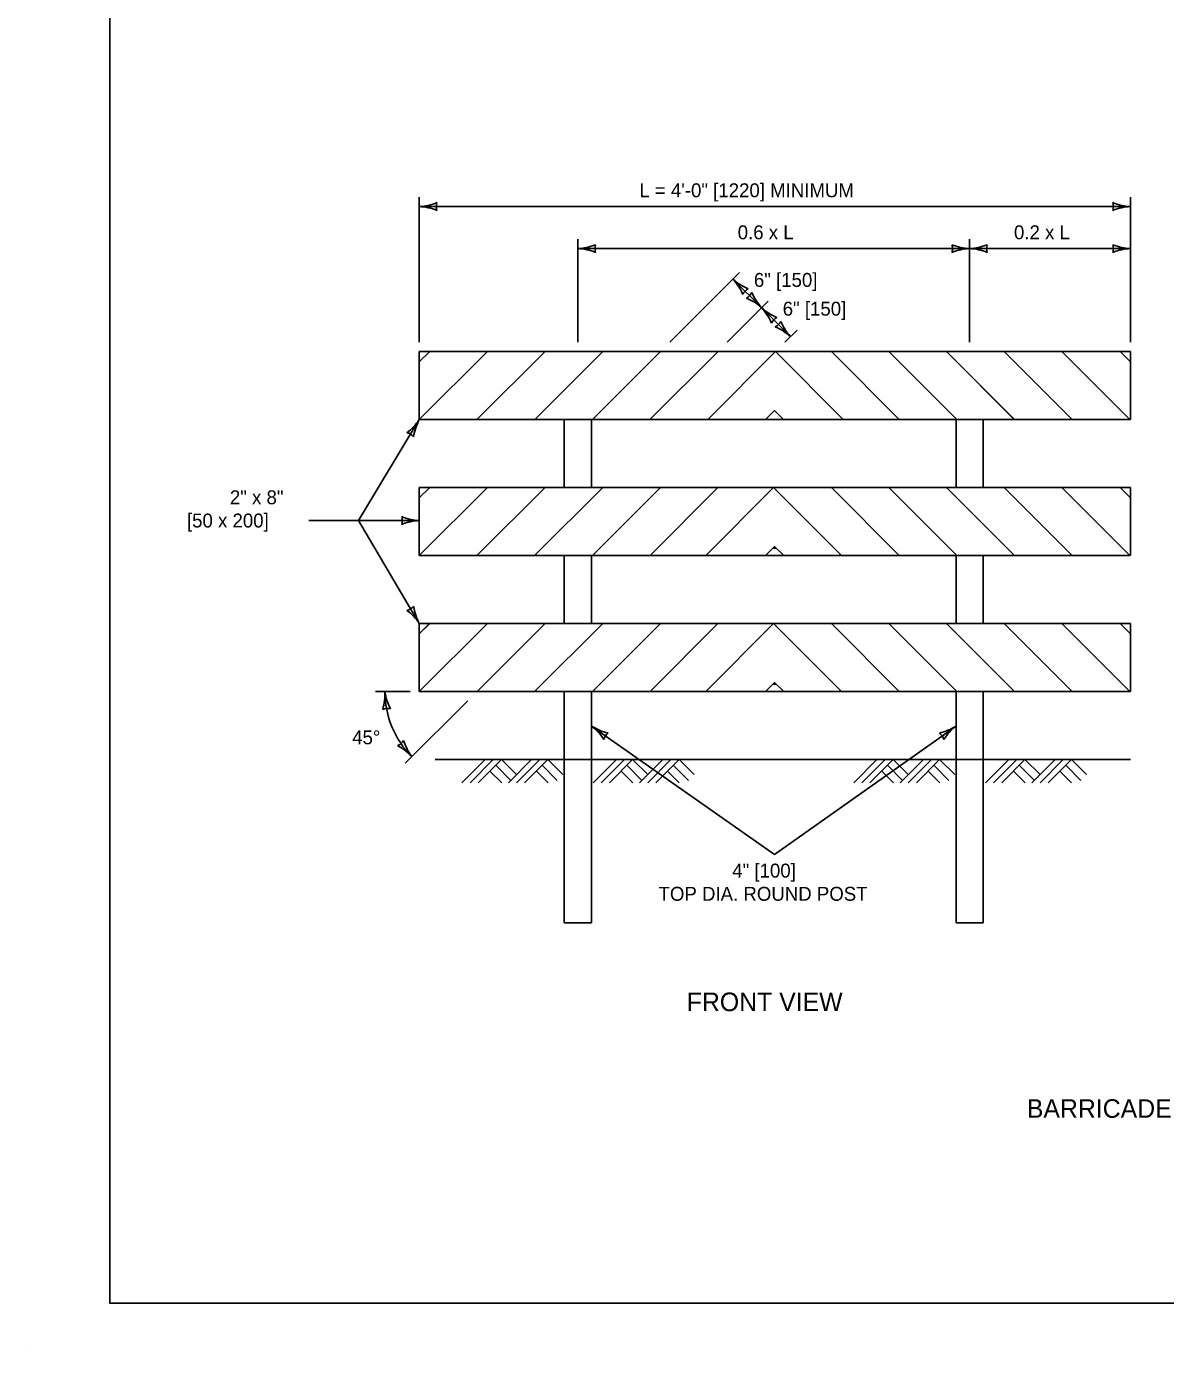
# Model space of a CAD drawing. Extents: x 49991.4 to 50021, y 49987.6 to 50011.4.
# Drawn here: x 49999.02 to 50003.93, y 49987.6 to 49993.3 of the extents above; entities that cross this region are included whole.
import ezdxf

# ---------------------------------------------------------------- set-up
doc = ezdxf.new("R2010")
doc.units = 0
for name, color, linetype in [('Level 1', 7, 'Continuous'), ('Level 2', 7, 'Continuous'), ('Level 3', 7, 'Continuous'), ('Level 4', 7, 'Continuous')]:
    doc.layers.add(name, color=color, linetype=linetype)

msp = doc.modelspace()

# ---------------------------------------------------------------- linework, layer by layer
at = {"layer": 'Level 1'}
for p, q in [((50003.7807, 49991.8982), (50000.717, 49991.8982)), ((50000.717, 49991.6053), (50000.717, 49991.8982)), ((50000.717, 49991.8982), (50000.717, 49991.6053)), ((50000.717, 49991.8539), (50000.717, 49991.8982)), ((50000.717, 49991.8982), (50000.7608, 49991.8977)), ((50000.717, 49991.6053), (50001.01, 49991.8982)), ((50000.7608, 49991.8977), (50000.717, 49991.8539)), ((50000.7608, 49991.8977), (50000.717, 49991.8539)), ((50001.2585, 49991.8982), (50000.9653, 49991.605)), ((50001.01, 49991.8982), (50001.2585, 49991.8982)), ((50001.2137, 49991.6049), (50001.507, 49991.8982)), ((50001.7558, 49991.8982), (50001.463, 49991.6055)), ((50001.507, 49991.8982), (50001.7558, 49991.8982)), ((50001.7105, 49991.6053), (50002.0031, 49991.8979)), ((50002.2519, 49991.8982), (50001.9593, 49991.6056)), ((50002.0031, 49991.8979), (50002.2519, 49991.8982)), ((50002.2519, 49991.8982), (50002.492, 49991.898)), ((50002.5424, 49991.6058), (50002.2519, 49991.8982)), ((50002.492, 49991.898), (50002.7841, 49991.6058)), ((50003.0321, 49991.6055), (50002.7392, 49991.8985)), ((50003.0321, 49991.6055), (50002.7392, 49991.8985)), ((50002.7392, 49991.8985), (50002.9876, 49991.8985)), ((50003.0321, 49991.6055), (50002.7392, 49991.8985)), ((50002.7392, 49991.8985), (50002.9876, 49991.8985)), ((50003.0321, 49991.6055), (50002.7392, 49991.8985)), ((50002.9876, 49991.8985), (50003.277, 49991.6091)), ((50002.9876, 49991.8985), (50003.2808, 49991.6055)), ((50003.2366, 49991.8982), (50003.4853, 49991.8982)), ((50003.5295, 49991.6054), (50003.2366, 49991.8982)), ((50003.4853, 49991.8982), (50003.7782, 49991.6053)), ((50003.7809, 49991.8536), (50003.7361, 49991.8984)), ((50003.7361, 49991.8984), (50003.7807, 49991.8982)), ((50003.7809, 49991.8536), (50003.7361, 49991.8984)), ((50003.7807, 49991.6053), (50003.7807, 49991.8982)), ((50003.7807, 49991.8982), (50003.7809, 49991.8536)), ((50002.2086, 49991.6053), (50002.2475, 49991.6442)), ((50002.2086, 49991.6053), (50002.2475, 49991.6442)), ((50002.2475, 49991.6442), (50002.287, 49991.6049)), ((50002.2475, 49991.6442), (50002.287, 49991.6049)), ((50000.9653, 49991.605), (50000.717, 49991.6053)), ((50000.717, 49991.6053), (50003.7807, 49991.6053)), ((50001.463, 49991.6055), (50001.2137, 49991.6049)), ((50001.3416, 49991.3124), (50001.3416, 49991.6053)), ((50001.4587, 49991.3124), (50001.4587, 49991.6033)), ((50001.9593, 49991.6056), (50001.7105, 49991.6053)), ((50002.287, 49991.6049), (50002.2086, 49991.6053)), ((50002.7841, 49991.6058), (50002.5424, 49991.6058)), ((50003.0291, 49991.3124), (50003.0291, 49991.6053)), ((50003.2808, 49991.6055), (50003.0321, 49991.6055)), ((50003.2808, 49991.6055), (50003.0321, 49991.6055)), ((50003.1462, 49991.3124), (50003.1462, 49991.6053)), ((50003.7782, 49991.6053), (50003.5295, 49991.6054)), ((50000.717, 49991.0195), (50000.717, 49991.3124)), ((50000.717, 49991.3124), (50000.717, 49991.0195)), ((50003.7807, 49991.3124), (50000.717, 49991.3124)), ((50000.717, 49991.3124), (50003.7807, 49991.3124)), ((50000.717, 49991.0195), (50001.01, 49991.3124)), ((50000.717, 49991.2681), (50000.717, 49991.3124)), ((50000.717, 49991.3124), (50000.7608, 49991.3119)), ((50003.7807, 49991.3124), (50000.717, 49991.3124)), ((50000.7608, 49991.3119), (50000.717, 49991.2681)), ((50000.7608, 49991.3119), (50000.717, 49991.2681)), ((50001.2585, 49991.3124), (50000.9653, 49991.0192)), ((50001.01, 49991.3124), (50001.2585, 49991.3124)), ((50001.2137, 49991.0191), (50001.507, 49991.3124)), ((50001.7558, 49991.3124), (50001.463, 49991.0197)), ((50001.7558, 49991.3124), (50001.5062, 49991.3131)), ((50001.7123, 49991.0213), (50002.0031, 49991.3121)), ((50002.2435, 49991.3121), (50001.951, 49991.0198)), ((50002.0031, 49991.3121), (50002.2435, 49991.3121)), ((50002.2434, 49991.312), (50002.492, 49991.3122)), ((50002.5355, 49991.02), (50002.2434, 49991.312)), ((50002.492, 49991.3122), (50002.7841, 49991.02)), ((50003.0321, 49991.0197), (50002.7392, 49991.3127)), ((50002.7392, 49991.3127), (50002.9876, 49991.3127)), ((50002.9876, 49991.3127), (50003.2808, 49991.0195)), ((50003.2366, 49991.3124), (50003.4853, 49991.3124)), ((50003.5295, 49991.0196), (50003.2366, 49991.3124)), ((50003.4853, 49991.3124), (50003.7782, 49991.0195)), ((50003.7809, 49991.2678), (50003.7361, 49991.3126)), ((50003.7809, 49991.2678), (50003.7361, 49991.3126)), ((50003.7361, 49991.3126), (50003.7807, 49991.3124)), ((50003.7807, 49991.0195), (50003.7807, 49991.3124)), ((50003.7807, 49991.3124), (50003.7809, 49991.2678)), ((50002.2086, 49991.0195), (50002.2475, 49991.0584)), ((50002.2086, 49991.0195), (50002.2475, 49991.0584)), ((50002.2086, 49991.0195), (50002.2475, 49991.0584)), ((50002.2408, 49991.0517), (50002.2542, 49991.0517)), ((50002.2475, 49991.0584), (50002.287, 49991.0191)), ((50002.2475, 49991.0584), (50002.287, 49991.0191)), ((50001.9868, 49991.0195), (50000.717, 49991.0195)), ((50000.717, 49991.0195), (50001.2137, 49991.0191)), ((50000.9653, 49991.0192), (50000.717, 49991.0195)), ((50000.717, 49991.0195), (50001.2137, 49991.0191)), ((50001.2137, 49991.0191), (50000.717, 49991.0195)), ((50000.717, 49991.0195), (50003.7782, 49991.0195)), ((50001.2137, 49991.0191), (50001.463, 49991.0197)), ((50001.3416, 49990.7265), (50001.3416, 49991.0195)), ((50001.4587, 49990.7265), (50001.4587, 49991.0195)), ((50001.951, 49991.0198), (50001.7123, 49991.0213)), ((50001.9593, 49991.0198), (50001.9593, 49991.0198)), ((50002.287, 49991.0191), (50002.2086, 49991.0195)), ((50002.7841, 49991.02), (50002.5355, 49991.02)), ((50003.0291, 49990.7265), (50003.0291, 49991.0195)), ((50003.2808, 49991.0195), (50003.0321, 49991.0197)), ((50003.1462, 49990.7265), (50003.1462, 49991.0195)), ((50003.7782, 49991.0195), (50003.5295, 49991.0196)), ((50000.717, 49990.4336), (50000.717, 49990.7265)), ((50000.717, 49990.7265), (50000.717, 49990.4336)), ((50003.7807, 49990.7265), (50000.717, 49990.7265)), ((50000.717, 49990.7265), (50003.7807, 49990.7265)), ((50000.717, 49990.4336), (50001.01, 49990.7265)), ((50000.717, 49990.6822), (50000.717, 49990.7265)), ((50000.717, 49990.7265), (50000.7613, 49990.7265)), ((50000.7613, 49990.7265), (50000.717, 49990.6822)), ((50003.7807, 49990.7265), (50000.717, 49990.7265)), ((50000.7608, 49990.726), (50000.717, 49990.6822)), ((50001.2585, 49990.7265), (50000.9656, 49990.4336)), ((50001.01, 49990.7265), (50001.2585, 49990.7265)), ((50001.2137, 49990.4332), (50001.507, 49990.7265)), ((50001.7558, 49990.7265), (50001.463, 49990.4338)), ((50001.7558, 49990.7265), (50001.5062, 49990.7272)), ((50001.7123, 49990.4354), (50002.0031, 49990.7262)), ((50002.2435, 49990.7262), (50001.951, 49990.4339)), ((50002.0031, 49990.7262), (50002.2435, 49990.7262)), ((50002.2434, 49990.7261), (50002.492, 49990.7263)), ((50002.5355, 49990.4341), (50002.2434, 49990.7261)), ((50002.492, 49990.7263), (50002.7841, 49990.4341)), ((50003.0321, 49990.4338), (50002.7392, 49990.7268)), ((50002.7392, 49990.7268), (50002.9876, 49990.7268)), ((50002.9876, 49990.7268), (50003.2808, 49990.4336)), ((50003.2366, 49990.7265), (50003.4853, 49990.7265)), ((50003.5295, 49990.4337), (50003.2366, 49990.7265)), ((50003.4853, 49990.7265), (50003.7782, 49990.4336)), ((50003.7809, 49990.6819), (50003.7361, 49990.7267)), ((50003.7809, 49990.6819), (50003.7361, 49990.7267)), ((50003.7361, 49990.7267), (50003.7807, 49990.7265)), ((50003.7807, 49990.4336), (50003.7807, 49990.7265)), ((50003.7807, 49990.7265), (50003.7809, 49990.6819)), ((50002.2086, 49990.4336), (50002.2475, 49990.4725)), ((50002.2086, 49990.4336), (50002.2475, 49990.4725)), ((50002.2086, 49990.4336), (50002.2475, 49990.4725)), ((50002.2475, 49990.4725), (50002.287, 49990.4332)), ((50002.2475, 49990.4725), (50002.287, 49990.4332)), ((50003.7807, 49990.4336), (50000.717, 49990.4336)), ((50000.9656, 49990.4336), (50000.717, 49990.4336)), ((50000.9656, 49990.4336), (50000.717, 49990.4336)), ((50000.7173, 49990.4339), (50000.9656, 49990.4336)), ((50001.2137, 49990.4332), (50001.463, 49990.4338)), ((50001.2141, 49990.4336), (50001.2137, 49990.4332)), ((50001.9868, 49990.4336), (50001.2141, 49990.4336)), ((50001.3416, 49990.1408), (50001.3416, 49990.4336)), ((50001.4587, 49990.1408), (50001.4587, 49990.4336)), ((50001.951, 49990.4339), (50001.7123, 49990.4354)), ((50001.9593, 49990.4339), (50001.9593, 49990.4339)), ((50002.287, 49990.4332), (50002.2086, 49990.4336)), ((50002.2408, 49990.4658), (50002.2542, 49990.4658)), ((50002.7841, 49990.4341), (50002.5355, 49990.4341)), ((50003.0291, 49990.1408), (50003.0291, 49990.4336)), ((50003.2808, 49990.4336), (50003.0321, 49990.4338)), ((50003.1462, 49990.1408), (50003.1462, 49990.4336)), ((50003.7782, 49990.4336), (50003.5295, 49990.4337)), ((50003.7807, 49990.1408), (50000.7851, 49990.1408)), ((50000.9008, 49990.0408), (50001.0008, 49990.1408)), ((50000.9358, 49990.0408), (50001.0358, 49990.1408)), ((50000.9708, 49990.0408), (50001.0708, 49990.1408)), ((50001.0708, 49990.1408), (50001.1358, 49990.0758)), ((50001.1008, 49990.0408), (50001.2008, 49990.1408)), ((50001.1358, 49990.0408), (50001.2358, 49990.1408)), ((50001.1708, 49990.0408), (50001.2708, 49990.1408)), ((50001.2708, 49990.1408), (50001.3358, 49990.0758)), ((50001.4658, 49990.0408), (50001.5658, 49990.1408)), ((50001.5008, 49990.0408), (50001.6008, 49990.1408)), ((50001.5358, 49990.0408), (50001.6358, 49990.1408)), ((50001.6358, 49990.1408), (50001.7008, 49990.0758)), ((50001.6658, 49990.0408), (50001.7658, 49990.1408)), ((50001.7008, 49990.0408), (50001.8008, 49990.1408)), ((50001.7358, 49990.0408), (50001.8358, 49990.1408)), ((50001.8358, 49990.1408), (50001.9008, 49990.0758)), ((50002.5885, 49990.0408), (50002.6885, 49990.1408)), ((50002.6235, 49990.0408), (50002.7235, 49990.1408)), ((50002.6585, 49990.0408), (50002.7585, 49990.1408)), ((50002.7585, 49990.1408), (50002.8235, 49990.0758)), ((50002.7885, 49990.0408), (50002.8885, 49990.1408)), ((50002.8235, 49990.0408), (50002.9235, 49990.1408)), ((50002.8585, 49990.0408), (50002.9585, 49990.1408)), ((50002.9585, 49990.1408), (50003.0235, 49990.0758)), ((50003.1563, 49990.0408), (50003.2563, 49990.1408)), ((50003.1913, 49990.0408), (50003.2913, 49990.1408)), ((50003.2263, 49990.0408), (50003.3263, 49990.1408)), ((50003.3263, 49990.1408), (50003.3913, 49990.0758)), ((50003.3563, 49990.0408), (50003.4563, 49990.1408)), ((50003.3913, 49990.0408), (50003.4913, 49990.1408)), ((50003.4263, 49990.0408), (50003.5263, 49990.1408)), ((50003.5263, 49990.1408), (50003.5913, 49990.0758)), ((50001.0213, 49990.0913), (50001.0718, 49990.0408)), ((50001.0461, 49990.1161), (50001.1111, 49990.0511)), ((50001.2213, 49990.0913), (50001.2718, 49990.0408)), ((50001.2461, 49990.1161), (50001.3111, 49990.0511)), ((50001.5863, 49990.0913), (50001.6368, 49990.0408)), ((50001.6111, 49990.1161), (50001.6761, 49990.0511)), ((50001.7863, 49990.0913), (50001.8368, 49990.0408)), ((50001.8111, 49990.1161), (50001.8761, 49990.0511)), ((50002.709, 49990.0913), (50002.7595, 49990.0408)), ((50002.7338, 49990.1161), (50002.7988, 49990.0511)), ((50002.909, 49990.0913), (50002.9595, 49990.0408)), ((50002.9338, 49990.1161), (50002.9988, 49990.0511)), ((50003.2768, 49990.0913), (50003.3273, 49990.0408)), ((50003.3016, 49990.1161), (50003.3666, 49990.0511)), ((50003.4768, 49990.0913), (50003.5273, 49990.0408)), ((50003.5016, 49990.1161), (50003.5666, 49990.0511)), ((49999.0245, 49987.5988), (49999.0245, 49987.5988))]:
    msp.add_line(p, q, dxfattribs=at)
msp.add_lwpolyline([(49999.3835, 49998.9992), (50016.7501, 49998.9992), (50016.7501, 49987.7988), (49999.3835, 49987.7988)], close=True, dxfattribs=at)
at = {"layer": 'Level 3'}
for p, q in [((50000.717, 49992.5631), (50000.717, 49991.9382)), ((50000.717, 49992.5231), (50003.7807, 49992.5231)), ((50003.7807, 49992.5631), (50003.7807, 49991.9382)), ((50001.4001, 49992.3821), (50001.4001, 49991.9382)), ((50003.0876, 49992.3821), (50003.0876, 49991.9382)), ((50001.4001, 49992.3421), (50003.0876, 49992.3421)), ((50003.0876, 49992.3421), (50003.7807, 49992.3421)), ((50001.7958, 49991.9382), (50002.0965, 49992.2389)), ((50002.0682, 49992.2106), (50002.192, 49992.0869)), ((50002.0434, 49991.9382), (50002.2203, 49992.1152)), ((50002.192, 49992.0869), (50002.3163, 49991.9626)), ((50002.2919, 49991.9382), (50002.3446, 49991.9909)), ((50000.717, 49991.6053), (50000.4554, 49991.1704)), ((50000.4554, 49991.1704), (50000.2409, 49991.1704)), ((50000.4554, 49991.1704), (50000.717, 49990.7265)), ((50000.717, 49991.1704), (50000.4554, 49991.1704)), ((50000.677, 49990.4336), (50000.5287, 49990.4336)), ((50000.6567, 49990.1247), (50000.9256, 49990.3936)), ((50001.4587, 49990.2851), (50002.2477, 49989.7322)), ((50002.2477, 49989.7322), (50003.0291, 49990.2851))]:
    msp.add_line(p, q, dxfattribs=at)
for centre, radius, start, end in [((50000.7055, 49992.7558), 0.233, 272.8273, 292.0772), ((50000.7078, 49992.301), 0.2223, 67.456, 87.6395), ((50000.8452, 49992.5231), 0.0548, 162.1388, 197.8612), ((50003.7899, 49992.7452), 0.2223, 247.456, 267.6395), ((50003.6525, 49992.5231), 0.0548, 342.1388, 17.8612), ((50003.7922, 49992.2904), 0.233, 92.8273, 112.0772), ((50001.3886, 49992.5748), 0.233, 272.8273, 292.0772), ((50001.5283, 49992.3421), 0.0548, 162.1388, 197.8612), ((50003.0968, 49992.5642), 0.2223, 247.456, 267.6395), ((50002.9594, 49992.3421), 0.0548, 342.1388, 17.8612), ((50003.0761, 49992.5748), 0.233, 272.8273, 292.0772), ((50003.2158, 49992.3421), 0.0548, 162.1388, 197.8612), ((50003.7899, 49992.5642), 0.2223, 247.456, 267.6395), ((50003.6525, 49992.3421), 0.0548, 342.1388, 17.8612), ((50001.3909, 49992.12), 0.2223, 67.456, 87.6395), ((50003.0991, 49992.1094), 0.233, 92.8273, 112.0772), ((50003.0784, 49992.12), 0.2223, 67.456, 87.6395), ((50003.7922, 49992.1094), 0.233, 92.8273, 112.0772), ((50001.9047, 49992.0599), 0.2223, 22.4791, 42.6626), ((50002.2246, 49992.3833), 0.233, 227.8504, 247.1002), ((50002.1589, 49992.12), 0.0548, 117.1619, 152.8842), ((50002.1013, 49992.1775), 0.0548, 297.1619, 332.8842), ((50002.0357, 49991.9141), 0.233, 47.8504, 67.1002), ((50002.3555, 49992.2376), 0.2223, 202.4791, 222.6626), ((50002.0285, 49991.9362), 0.2223, 22.479, 42.6625), ((50002.3484, 49992.2596), 0.233, 227.8503, 247.1001), ((50002.2827, 49991.9963), 0.0548, 117.1618, 152.8841), ((50002.2257, 49992.0533), 0.0548, 297.1618, 332.8841), ((50002.4798, 49992.1133), 0.2223, 202.479, 222.6625), ((50002.16, 49991.7899), 0.233, 47.8503, 67.1001), ((50000.5314, 49991.7276), 0.2223, 306.4284, 326.6119), ((50000.9223, 49991.4952), 0.233, 151.7997, 171.0495), ((50000.6509, 49991.4954), 0.0548, 41.1112, 76.8335), ((50000.7262, 49991.3925), 0.2223, 247.456, 267.6395), ((50000.5888, 49991.1704), 0.0548, 342.1388, 17.8612), ((50000.7285, 49990.9377), 0.233, 92.8273, 112.0772), ((50000.6518, 49990.8369), 0.0548, 282.7098, 318.4322), ((50000.5225, 49990.5982), 0.233, 33.3983, 52.6482), ((50000.9129, 49990.8316), 0.2223, 188.027, 208.2105), ((50000.3467, 49990.4219), 0.2223, 342.8266, 3.0101), ((50000.7993, 49990.4668), 0.233, 188.1979, 207.4478), ((50000.9656, 49990.4336), 0.3969, 180, 225), ((50000.5807, 49990.3059), 0.0548, 77.5094, 113.2318), ((50001.3237, 49990.1084), 0.2223, 32.4348, 52.6183), ((50001.5828, 49990.4823), 0.233, 237.8061, 257.0559), ((50001.5637, 49990.2115), 0.0548, 127.1176, 162.8399), ((50002.9083, 49990.4717), 0.2223, 282.7383, 302.9218), ((50002.9244, 49990.211), 0.0548, 17.4211, 53.1435), ((50003.1729, 49990.1018), 0.233, 128.1096, 147.3595), ((50000.6032, 49990.2517), 0.0548, 291.7562, 327.4785), ((50000.513, 49989.9957), 0.233, 42.4447, 61.6945), ((50000.8619, 49990.2875), 0.2223, 197.0734, 217.2569)]:
    msp.add_arc(centre, radius, start, end, dxfattribs=at)
at = {"layer": 'Level 4'}
for p, q in [((50001.3416, 49989.4376), (50001.3416, 49990.1408)), ((50001.4587, 49990.1408), (50001.4587, 49989.4376)), ((50003.0291, 49989.4376), (50003.0291, 49990.1408)), ((50003.1462, 49990.1408), (50003.1462, 49989.4376)), ((50001.4587, 49989.4376), (50001.3416, 49989.4376)), ((50003.1462, 49989.4376), (50003.0291, 49989.4376))]:
    msp.add_line(p, q, dxfattribs=at)

# ---------------------------------------------------------------- texts
at = {"layer": 'Level 2'}
for s, height, p in [('L = 4\'-0" [1220] MINIMUM', 0.06, (50001.6648, 49992.5631)), ('0.6 x L', 0.06, (50002.0886, 49992.3821)), ('0.2 x L', 0.06, (50003.2789, 49992.3821)), ('2" x 8"', 0.06, (49999.9009, 49991.2404)), ('[50 x 200]', 0.06, (49999.7159, 49991.1404)), ('45°', 0.06, (50000.4277, 49990.2064)), ('4" [100]', 0.06, (50002.0652, 49989.6322)), ('TOP DIA. ROUND POST', 0.06, (50001.7476, 49989.5322)), ('FRONT VIEW', 0.08, (50001.8691, 49989.0568)), ('BARRICADE DETAILS', 0.08, (50003.3342, 49988.5972))]:
    msp.add_text(s, height=height, dxfattribs=at).set_placement(p)
for p in [(50002.1584, 49992.177), (50002.2825, 49992.0531)]:
    msp.add_text('6" [150]', height=0.06, rotation=360, dxfattribs=at).set_placement(p)

doc.saveas('drawing.dxf')
